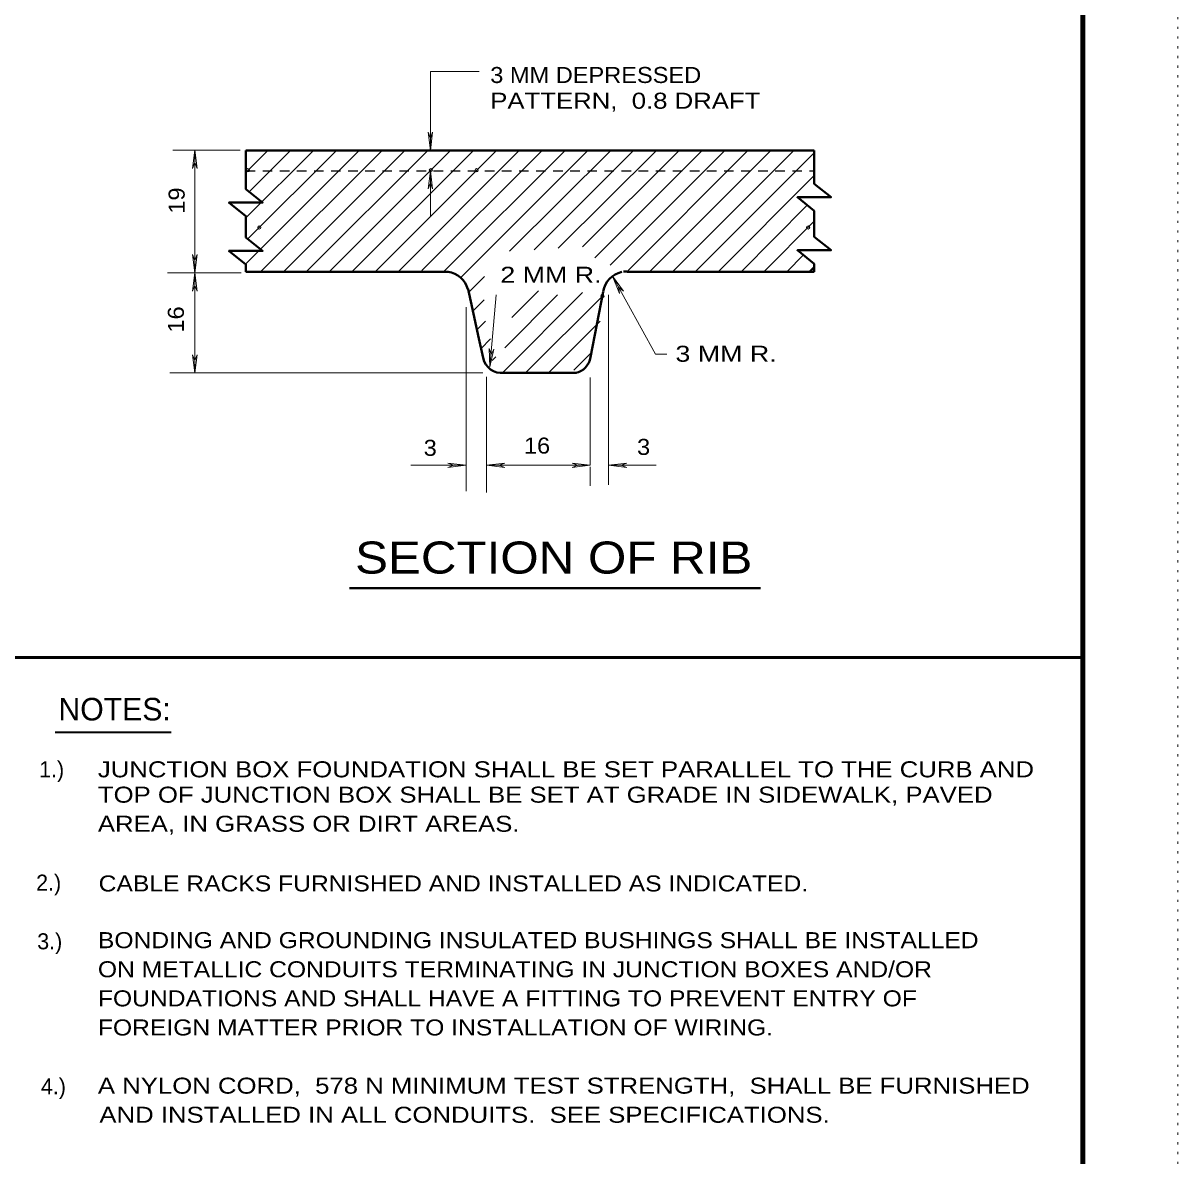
# Model space of a CAD drawing. Extents: x 312583 to 312854, y 144419 to 144597.
# Drawn here: x 312798.7 to 312853.5, y 144489.3 to 144543.1 of the extents above; entities that cross this region are included whole.
import ezdxf
from ezdxf.enums import TextEntityAlignment as Align

# ---------------------------------------------------------------- set-up
doc = ezdxf.new("R2010")
doc.units = 0
doc.header["$LTSCALE"] = 0.3
doc.header["$PDMODE"] = 32
doc.header["$PDSIZE"] = 0.15
doc.linetypes.add('DOTTED', pattern=[1.5, 0.3, -1.2])
doc.linetypes.add('SHORT_DASHED', pattern=[2.7, 1.5, -1.2])
for name, color, linetype, lineweight in [('1', 7, 'Continuous', 40), ('2', 7, 'Continuous', 13), ('63', 7, 'DOTTED', 13)]:
    doc.layers.add(name, color=color, linetype=linetype, lineweight=lineweight)

msp = doc.modelspace()

# ---------------------------------------------------------------- linework, layer by layer
at = {"layer": '1', "lineweight": 158}
msp.add_line((312849, 144423.1446), (312849, 144585.0846), dxfattribs=at)
at = {"layer": '1'}
for p, q in [((312809.3017, 144537.0189), (312836.2577, 144537.0189)), ((312809.3017, 144535.1866), (312809.3017, 144537.0189)), ((312836.2577, 144535.4396), (312836.2577, 144537.0189)), ((312836.2577, 144532.9249), (312836.2577, 144534.1592)), ((312809.3017, 144532.8942), (312809.3017, 144533.9216)), ((312809.3017, 144531.2689), (312809.3017, 144531.6292)), ((312809.3017, 144531.2689), (312818.8927, 144531.2689)), ((312827.3873, 144531.2689), (312836.2577, 144531.2689)), ((312836.2577, 144531.2689), (312836.2577, 144531.6446)), ((312819.8433, 144530.4409), (312820.3493, 144528.1102)), ((312826.245, 144530.3182), (312825.6547, 144527.2132)), ((312820.357, 144528.1102), (312820.564, 144527.1826)), ((312821.5377, 144526.4772), (312824.98, 144526.4772)), ((312814.2193, 144516.2593), (312833.7085, 144516.2593))]:
    msp.add_line(p, q, dxfattribs=at)
at = {"layer": '1', "linetype": 'SHORT_DASHED', "lineweight": 25}
msp.add_line((312809.3017, 144536.0606), (312836.2577, 144536.0606), dxfattribs=at)
at = {"layer": '1', "lineweight": 53}
msp.add_line((312849, 144512.9685), (312796.6103, 144512.9685), dxfattribs=at)
at = {"layer": '1', "lineweight": 35}
msp.add_line((312800.2695, 144509.4382), (312805.7589, 144509.4382), dxfattribs=at)
at = {"layer": '1'}
for centre, radius, start, end in [((312818.7317, 144530.1342), 1.1458, 15.77569, 81.73987), ((312827.3797, 144530.1419), 1.1458, 102.6945, 170.22132), ((312827.3797, 144530.1419), 1.1458, 90.25769, 98.00326), ((312821.4273, 144527.3496), 0.8793, 190.95024, 277.2099), ((312824.7746, 144527.3329), 0.8793, 280.95024, 352.12246)]:
    msp.add_arc(centre, radius, start, end, dxfattribs=at)
at = {"layer": '2'}
for p, q in [((312818.057, 144540.7679), (312818.057, 144537.0189)), ((312818.057, 144540.7679), (312820.3647, 144540.7679)), ((312817.9497, 144537.8852), (312818.057, 144537.6092)), ((312818.057, 144537.0189), (312817.9497, 144537.8852)), ((312818.1643, 144537.8852), (312818.057, 144537.6092)), ((312818.057, 144537.0189), (312818.1643, 144537.8852)), ((312809.041, 144537.0342), (312805.8517, 144537.0342)), ((312806.8867, 144537.0342), (312806.7793, 144536.1679)), ((312806.8867, 144537.0342), (312806.994, 144536.1679)), ((312809.3017, 144535.9762), (312810.3443, 144537.0189)), ((312809.3017, 144533.8296), (312812.514, 144537.0189)), ((312809.3017, 144531.6522), (312814.6837, 144537.0189)), ((312809.3937, 144532.8252), (312813.6027, 144537.0266)), ((312809.4627, 144535.0639), (312811.4253, 144537.0189)), ((312810.0147, 144531.2766), (312815.7647, 144537.0189)), ((312811.088, 144531.2689), (312816.8457, 144537.0189)), ((312812.1997, 144531.2919), (312817.9343, 144537.0189)), ((312813.296, 144531.2919), (312819.0153, 144537.0189)), ((312814.3847, 144531.3072), (312820.104, 144537.0189)), ((312815.481, 144531.3149), (312821.1773, 144537.0112)), ((312816.5697, 144531.3149), (312822.2737, 144537.0189)), ((312817.6583, 144531.3226), (312823.3547, 144537.0189)), ((312818.7317, 144531.3149), (312824.4357, 144537.0112)), ((312819.4677, 144530.9699), (312825.5243, 144537.0189)), ((312821.8137, 144532.2426), (312826.6053, 144537.0189)), ((312822.9713, 144532.3116), (312827.694, 144537.0189)), ((312824.1213, 144532.3806), (312828.775, 144537.0189)), ((312825.2713, 144532.4496), (312829.856, 144537.0189)), ((312825.8463, 144531.9282), (312830.9447, 144537.0189)), ((312826.5823, 144531.5756), (312832.0257, 144537.0189)), ((312827.3643, 144531.2689), (312833.1143, 144537.0189)), ((312828.4453, 144531.2689), (312834.1953, 144537.0189)), ((312829.534, 144531.2689), (312835.284, 144537.0189)), ((312830.615, 144531.2689), (312836.2577, 144536.9116)), ((312806.7793, 144536.1679), (312806.8867, 144536.4439)), ((312806.994, 144536.1679), (312806.8867, 144536.4439)), ((312818.057, 144536.0606), (312817.9497, 144535.1942)), ((312818.057, 144536.0606), (312818.057, 144533.8679)), ((312818.057, 144536.0606), (312818.1643, 144535.1942)), ((312831.696, 144531.2689), (312836.2577, 144535.8306)), ((312817.9497, 144535.1942), (312818.057, 144535.4702)), ((312818.1643, 144535.1942), (312818.057, 144535.4702)), ((312832.7847, 144531.2689), (312835.928, 144534.4199)), ((312833.8657, 144531.2689), (312836.2577, 144533.6609)), ((312806.7793, 144532.0816), (312806.8867, 144531.8056)), ((312806.8867, 144531.2152), (312806.7793, 144532.0816)), ((312806.994, 144532.0816), (312806.8867, 144531.8056)), ((312806.8867, 144531.2152), (312806.994, 144532.0816)), ((312834.9543, 144531.2689), (312835.744, 144532.0662)), ((312809.0793, 144531.2152), (312805.5987, 144531.2152)), ((312806.8867, 144531.2152), (312806.7793, 144530.3489)), ((312806.8867, 144531.2152), (312806.994, 144530.3489)), ((312819.828, 144530.2492), (312820.6177, 144531.0389)), ((312826.6973, 144531.0542), (312827.0193, 144530.2416)), ((312826.6973, 144531.0542), (312827.211, 144530.3489)), ((312806.7793, 144530.3489), (312806.8867, 144530.6249)), ((312806.994, 144530.3489), (312806.8867, 144530.6249)), ((312821.1773, 144530.1726), (312820.8783, 144526.7532)), ((312821.53, 144526.5232), (312825.2713, 144530.2799)), ((312821.5837, 144527.6656), (312824.0907, 144530.1726)), ((312821.921, 144529.0992), (312823.186, 144530.3642)), ((312822.5803, 144526.4849), (312826.2143, 144530.1189)), ((312826.498, 144530.1726), (312826.498, 144521.1566)), ((312827.0193, 144530.2416), (312826.981, 144530.5406)), ((312827.211, 144530.3489), (312826.981, 144530.5406)), ((312819.7513, 144529.5976), (312819.7513, 144520.8652)), ((312820.0427, 144529.3752), (312820.6023, 144529.9426)), ((312820.3033, 144528.5549), (312820.6637, 144528.9229)), ((312823.6383, 144526.4619), (312826.0993, 144528.9229)), ((312820.449, 144527.6196), (312820.909, 144528.0872)), ((312820.8477, 144527.6272), (312820.932, 144527.3436)), ((312820.8783, 144526.7532), (312820.8477, 144527.6272)), ((312820.8783, 144526.7532), (312821.0623, 144527.6042)), ((312821.0623, 144527.6042), (312820.932, 144527.3436)), ((312824.865, 144526.6076), (312825.7237, 144527.4662)), ((312806.7793, 144527.3359), (312806.8867, 144527.0599)), ((312806.8867, 144526.4696), (312806.7793, 144527.3359)), ((312806.994, 144527.3359), (312806.8867, 144527.0599)), ((312806.8867, 144526.4696), (312806.994, 144527.3359)), ((312820.9933, 144527.0676), (312821.1543, 144527.2362)), ((312820.541, 144526.4696), (312805.706, 144526.4696)), ((312820.7173, 144526.2932), (312820.7173, 144520.7962)), ((312825.6393, 144526.2549), (312825.6393, 144522.0919)), ((312819.7513, 144522.0919), (312817.1325, 144522.0919)), ((312818.885, 144522.1992), (312819.161, 144522.0919)), ((312819.7513, 144522.0919), (312818.885, 144522.1992)), ((312818.885, 144521.9846), (312819.161, 144522.0919)), ((312819.7513, 144522.0919), (312818.885, 144521.9846)), ((312820.7173, 144522.0919), (312821.5837, 144522.1992)), ((312825.6393, 144522.0919), (312820.7173, 144522.0919)), ((312820.7173, 144522.0919), (312821.5837, 144521.9846)), ((312821.5837, 144522.1992), (312821.3077, 144522.0919)), ((312821.5837, 144521.9846), (312821.3077, 144522.0919)), ((312824.773, 144522.1992), (312825.049, 144522.0919)), ((312825.6393, 144522.0919), (312824.773, 144522.1992)), ((312824.773, 144521.9846), (312825.049, 144522.0919)), ((312825.6393, 144522.0919), (312824.773, 144521.9846)), ((312825.6393, 144522.0152), (312825.6393, 144521.1106)), ((312826.498, 144522.0919), (312827.3643, 144522.1992)), ((312826.498, 144522.0919), (312827.3643, 144521.9846)), ((312828.7548, 144522.0919), (312826.498, 144522.0919)), ((312827.3643, 144522.1992), (312827.0883, 144522.0919)), ((312827.3643, 144521.9846), (312827.0883, 144522.0919))]:
    msp.add_line(p, q, dxfattribs=at)
for points in [[(312806.8867, 144537.0342), (312806.8867, 144531.2152), (312806.8867, 144526.4696)], [(312829.2657, 144527.3666), (312828.729, 144527.3666), (312826.6973, 144531.0542)]]:
    msp.add_lwpolyline(points, dxfattribs=at)
at = {"layer": '2', "lineweight": 40}
for points in [[(312809.3017, 144535.1866), (312810.099, 144534.5502), (312808.5043, 144534.5502), (312809.3017, 144533.9062)], [(312836.2577, 144535.4396), (312837.055, 144534.8032), (312835.4603, 144534.8032), (312836.2577, 144534.1592)], [(312809.3017, 144532.8942), (312810.099, 144532.2579), (312808.5043, 144532.2579), (312809.3017, 144531.6139)], [(312836.2577, 144532.9249), (312837.055, 144532.2886), (312835.4603, 144532.2886), (312836.2577, 144531.6446)], [(312836.0277, 144531.2612), (312836.0353, 144531.2689), (312836.2577, 144531.4912)]]:
    msp.add_lwpolyline(points, dxfattribs=at)
at = {"layer": '2'}
for p in [(312809.409, 144536.0836), (312818.08, 144536.0836), (312820.2497, 144536.0836), (312809.9457, 144533.3696), (312835.9663, 144533.3696), (312826.2143, 144530.1189)]:
    msp.add_point(p, dxfattribs=at)
at = {"layer": '63'}
msp.add_lwpolyline([(312601.2, 144418.5846), (312853.5, 144418.5846), (312853.5, 144596.7846)], dxfattribs=at)

# ---------------------------------------------------------------- texts
at = {"layer": '1'}
msp.add_text('NOTES:', height=1.07, dxfattribs=at).set_placement((312803.0846, 144509.9902), align=Align.CENTER)
for s, p in [('1.)   ', (312799.5051, 144507.2933)), ('2.)  ', (312799.3643, 144501.9197)), ('3.)', (312799.416, 144499.137)), ('4.)  ', (312799.5906, 144492.2598))]:
    msp.add_text(s, height=0.76, dxfattribs=at).set_placement(p)
for s, width, p in [('JUNCTION BOX FOUNDATION SHALL BE SET PARALLEL TO THE CURB AND  ', 1.2, (312802.2916, 144507.2934)), ('TOP OF JUNCTION BOX SHALL BE SET AT GRADE IN SIDEWALK, PAVED', 1.2, (312802.2916, 144506.0907)), ('AREA, IN GRASS OR DIRT AREAS.', 1.2, (312802.2916, 144504.7107)), ('CABLE RACKS FURNISHED AND INSTALLED AS INDICATED. ', 1.15, (312802.327, 144501.8798)), ('BONDING AND GROUNDING INSULATED BUSHINGS SHALL BE INSTALLED ', 1.15, (312802.2916, 144499.1907)), ('ON METALLIC CONDUITS TERMINATING IN JUNCTION BOXES AND/OR', 1.15, (312802.2916, 144497.8107)), ('FOUNDATIONS AND SHALL HAVE A FITTING TO PREVENT ENTRY OF', 1.15, (312802.2916, 144496.4307)), ('FOREIGN MATTER PRIOR TO INSTALLATION OF WIRING.', 1.15, (312802.2916, 144495.0507)), ('A NYLON CORD,  578 N MINIMUM TEST STRENGTH,  SHALL BE FURNISHED  ', 1.2, (312802.2916, 144492.2907)), ('AND INSTALLED IN ALL CONDUITS.  SEE SPECIFICATIONS. ', 1.2, (312802.3625, 144490.9107))]:
    msp.add_text(s, height=0.76, dxfattribs=dict(at, width=width)).set_placement(p)
at = {"layer": '2'}
for s, width, p in [('3 MM DEPRESSED', 1.1, (312820.8956, 144540.2207)), ('PATTERN,  0.8 DRAFT', 1.2, (312820.8956, 144539.0007)), ('2 MM R.', 1.25, (312821.3726, 144530.7457)), ('3 MM R.', 1.25, (312829.6762, 144527.0014)), ('3 ', 1.1, (312817.739, 144522.5394)), ('16 ', 1.1, (312822.4912, 144522.6458)), ('3 ', 1.1, (312827.8568, 144522.5826))]:
    msp.add_text(s, height=0.76, dxfattribs=dict(at, width=width)).set_placement(p)
at = {"layer": '2', "width": 1.1}
for s, p in [('19 ', (312806.4052, 144534.0222)), ('16 ', (312806.3688, 144528.3856))]:
    msp.add_text(s, height=0.76, rotation=90, dxfattribs=at).set_placement(p)
at = {"layer": '2', "width": 1.15}
msp.add_text('SECTION OF RIB', height=1.52, dxfattribs=at).set_placement((312823.9047, 144516.9552), align=Align.CENTER)

doc.saveas('drawing.dxf')
